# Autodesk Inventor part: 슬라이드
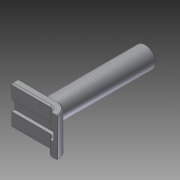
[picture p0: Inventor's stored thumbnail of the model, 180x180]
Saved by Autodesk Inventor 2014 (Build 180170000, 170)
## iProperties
Created: 2015-10
Part Number: 슬라이드
Document SubType Name: Modeling
Designer: mdu
Density: 7.86 g/cm^3
Material: 강철, 연강
Mass: 21.364 g
Surface Area: 19.6411 cm^2
Volume: 2.71806 cm^3
Appearance: 기본값
Author: mdu
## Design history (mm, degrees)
sketch "스케치1"
  geometry: L1 (10.279, 23.212)-(25.279, 23.212); L2 (10.279, 19.212)-(25.279, 19.212); L3 (25.279, 26.212)-(10.279, 26.212); L4 (10.279, 26.212)-(10.279, 16.212); L5 (10.279, 16.212)-(25.279, 16.212); C1 r 2 at (25.279, 21.212); A1 r 2 centre (25.279, 21.212) between (25.279, 23.212) and (25.279, 19.212) reference; A2 r 5 centre (25.279, 21.212) between (25.279, 26.212) and (25.279, 16.212); 1 further point
  constraints: 10 end point, 4 point on circle, 4 tangent, 3 parallel, 2 centre point, 2 coincident, 2 point on line, 1 horizontal, 1 perpendicular
  dimensions: "d0" = 4 diameter of C1; "d1" = 10 diameter of A2; "d4" = 15 distance from line of A2.centre L4
extrude "돌출1" new body sketch "스케치1" stored distance "d2" = 15; taper "d3" = 0 deg
sketch "스케치2"
  geometry: L1 (10.279, 26.212)-(10.279, 23.212) reference; L2 (10.279, 24.462)-(25.279, 24.462); L3 (27.779, 19.135)-(27.779, 6.212); L4 (27.779, 6.212)-(0.279, 6.212); L5 (0.279, 6.212)-(0.279, 24.462); L6 (10.279, 24.462)-(0.279, 24.462); A1 r 5 centre (25.279, 21.212) between (25.279, 16.212) and (25.279, 26.212) reference; A2 r 3.25 centre (25.279, 21.212) between (25.279, 24.462) and (27.779, 19.135); 1 further point
  constraints: 10 end point, 4 perpendicular, 2 point on circle, 1 centre point, 1 coincident, 1 parallel, 1 point on line, 1 tangent
  dimensions: "d5" = 6.5 diameter of A2; "d6" = 10 distance between parallel lines of L1 L5; "d7" = 10 distance from line of L4 A1.start; "d8" = 2.5 distance from line of L3 A1.centre
extrude "돌출2" cut sketch "스케치2" stored distance "d9" = 4; taper "d10" = 0 deg
sketch "스케치3"
  geometry: L1 (0, 15)-(0, 0) reference; C1 r 4 at (9.5, 7.5); 2 further points
  constraints: 1 centre point, 1 horizontal alignment, 1 midpoint
  dimensions: "d11" = 8 diameter of C1; "d12" = 9.5 distance from line of C1.centre L1
extrude "돌출3" join sketch "스케치3" distance "d13" = 40; taper "d14" = 0 deg
sketch "스케치4"
  geometry: C1 r 4 at (9.5, 7.5) reference; C2 r 4.65 at (9.5, 7.5); C3 r 6.75 at (9.5, 7.5); C4 r 5.5 at (9.5, 7.5); 1 further point
  constraints: 3 centre point, 3 coincident
  dimensions: "d15" = 9.3 diameter of C2; "d16" = 13.5 diameter of C3; "d19" = 11 diameter of C4
extrude "돌출4" cut sketch "스케치4" distance "d17" = 0.5; taper "d18" = 0 deg
sketch "스케치5"
  geometry: L1 (30.279, 21.212)-(7.279, 21.212); L2 (7.279, 21.212)-(7.279, 13.212); L3 (7.279, 13.212)-(31.947, 13.212); L4 (31.947, 13.212)-(31.947, 21.212); L5 (31.947, 21.212)-(30.279, 21.212); L6 (10.279, 16.212)-(10.279, 19.212) reference; A1 r 5 centre (25.279, 21.212) between (25.279, 16.212) and (25.279, 26.212) reference; 1 further point
  constraints: 10 end point, 2 perpendicular, 1 collinear, 1 horizontal, 1 parallel, 1 point on circle
  dimensions: "d20" = 3 distance between parallel lines of L2 L6; "d21" = 8 distance of L3.end L4.end
extrude "돌출5" cut sketch "스케치5" stored distance "d22" = 1; taper "d23" = 0 deg
chamfer "모따기1" distance "d24" = 0.5; stored, may be unused: second distance "d25" = 2, angle "d26" = 45 deg
hole "구멍1" diameter "d29" = 3.242; stored, may be unused: countersink angle "d33" = 90 deg, drill point angle "d35" = 118 deg; dims "d27" = 10, "d28" = 10, "d30" = 6, "d31" = 4, "d32" = 2, "d34" = 8
chamfer "모따기2" distance "d36" = 0.5; stored, may be unused: second distance "d37" = 2, angle "d38" = 45 deg
node "솔리드1"
node "참조1"
node "투영된 루프1"
